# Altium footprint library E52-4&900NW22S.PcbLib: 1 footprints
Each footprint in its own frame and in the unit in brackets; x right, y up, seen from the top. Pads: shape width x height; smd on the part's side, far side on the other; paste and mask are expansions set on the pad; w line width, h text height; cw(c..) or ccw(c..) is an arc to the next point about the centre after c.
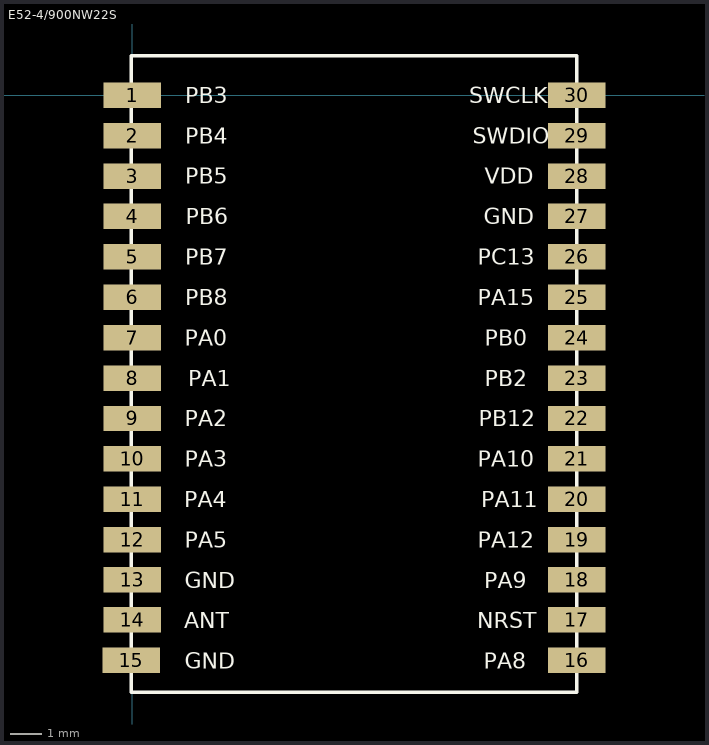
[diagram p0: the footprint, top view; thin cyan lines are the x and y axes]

## E52-4/900NW22S [mm] "20mm*14mm*2.8mm-S"
pads (30):
  rect 1.8x0.8 smd: 1(0,0) 2(0,-1.27) 3(0,-2.54) 4(0,-3.81) 5(0,-5.08) 6(0,-6.35) 7(0,-7.62) 8(0,-8.89) 9(0,-10.16) 10(0,-11.43) 11(0,-12.7) 12(0,-13.97) 13(0,-15.222) 14(0,-16.492) 15(-0.03,-17.762) 16(13.97,-17.762) 17(13.97,-16.492) 18(13.97,-15.222) 19(13.97,-13.97) 20(13.97,-12.7) 21(13.97,-11.43) 22(13.97,-10.16) 23(13.97,-8.89) 24(13.97,-7.62) 25(13.97,-6.35) 26(13.97,-5.08) 27(13.97,-3.81) 28(13.97,-2.54) 29(13.97,-1.27) 30(13.97,0)
Top Overlay:
  lines w0.1: -0.03,-18.762 13.97,-18.762 13.97,1.238 -0.03,1.238 -0.03,-18.762
  text "SWCLK" at 10.588,-0.25 h0.5
  text "SWDIO" at 10.708,-1.52 h0.5
  text "VDD" at 11.072,-2.79 h0.5
  text "GND" at 11.046,-4.06 h0.5
  text "PC13" at 10.863,-5.33 h0.5
  text "PA15" at 10.863,-6.6 h0.5
  text "PB0" at 11.072,-7.87 h0.5
  text "PB2" at 11.072,-9.14 h0.5
  text "PB12" at 10.889,-10.41 h0.5
  text "PA10" at 10.863,-11.68 h0.5
  text "PA11" at 10.97,-12.95 h0.5
  text "PA12" at 10.863,-14.22 h0.5
  text "PA9" at 11.058,-15.49 h0.5
  text "NRST" at 10.837,-16.76 h0.5
  text "PA8" at 11.046,-18.03 h0.5
  text "GND" at 1.648,-18.03 h0.5
  text "ANT" at 1.635,-16.76 h0.5
  text "GND" at 1.648,-15.49 h0.5
  text "PA5" at 1.648,-14.22 h0.5
  text "PA4" at 1.636,-12.95 h0.5
  text "PA3" at 1.648,-11.68 h0.5
  text "PA2" at 1.648,-10.41 h0.5
  text "PA1" at 1.755,-9.14 h0.5
  text "PA0" at 1.648,-7.87 h0.5
  text "PB8" at 1.674,-6.6 h0.5
  text "PB7" at 1.674,-5.33 h0.5
  text "PB6" at 1.686,-4.06 h0.5
  text "PB5" at 1.674,-2.79 h0.5
  text "PB4" at 1.662,-1.52 h0.5
  text "PB3" at 1.674,-0.25 h0.5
